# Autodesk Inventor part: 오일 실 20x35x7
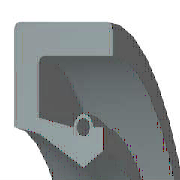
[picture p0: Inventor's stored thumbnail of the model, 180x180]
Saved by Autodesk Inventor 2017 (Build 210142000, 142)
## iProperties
IsCustomPart: 1
Created: 2012-02
Part Number: 오일 실 20x35x7
Material: 고무
Description: 회전 샤프트 립 유형 실 2 - 금속 케이스
Document SubType Name: Modeling
Standard: ISO 6194/1
Designer: mduedu
Standards Organization: ISO
Language: ko-KR
Size Designation: 20x35x7-유형 2
Categories: <MemberInstance><Categories><Category DisplayName="샤프트 부품" InternalName="7f7aeb1f-a693-4053-b835-cee3144e0d98" Mnemonic="SHFT"><Category DisplayName="실링" Intern
Density: 0.93 g/cm^3
Appearance: 고무 - 검은색 - 버전 1.1
Author: mduedu
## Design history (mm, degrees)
node "WorkPlane2"
node "WorkPoint1"
node "WorkPlane3"
body "Solid1"
node "스케치1"
revolve "회전1" stored, may be unused: angle "d37" = 360 deg
fillet "모깎기1" dims "d38" = 0.35 (= 0.05 x b)
sketch "스케치2"
  geometry: L1 (16, -0.35)-(16.8, -0.35); L2 (16, 0)-(16, -0.35); L3 (17.5, 0)-(16, 0); L4 (17.5, -7)-(17.5, 0); L5 (12.22, -7)-(17.5, -7); L6 (11.283, -4.2)-(12.22, -7); L7 (10.601, -3.72)-(11.283, -4.2); L8 (10, -1.925)-(10.601, -3.72); L9 (10.789, -1.05)-(10, -1.925); L10 (12.664, -1.05)-(10.789, -1.05); L11 (12.664, -1.925)-(12.664, -1.05); L12 (12.664, -5.6)-(12.664, -3.325); L13 (13.664, -5.6)-(12.664, -5.6); L14 (13.664, -6.3)-(13.664, -5.6); L15 (16.8, -6.3)-(13.664, -6.3); L16 (16.8, -0.35)-(16.8, -6.3); L17 (0, -15.959)-(0, 2.029); L18 (0, -15.959)-(0, 2.029); L19 (0, -19.557)-(0, 5.626) reference; L20 (-5.2, 0)-(31.2, 0) reference; A1 r 0.7 centre (12.664, -2.625) between (12.664, -3.325) and (12.664, -1.925)
  constraints: 36 end point, 7 vertical, 6 horizontal, 2 collinear, 2 point on circle, 1 centre point, 1 parallel, 1 point on line
  dimensions: "d2" = 0.35 distance of L2.start L1.start (= 0.05 x b); "d4" = 7 distance of L4.start L3.start (= b); "d6" = 0.7 horizontal distance of L1.end L3.start (= 0.1 x b); "d8" = 0.7 horizontal distance of L15.start L4.start (= 0.1 x b); "d10" = 0.7 distance of L14.start L13.start (= 0.1 x b); "d12" = 0.7 vertical distance of L1.end L10.start (= 0.1 x b); "d14" = 0.875 distance of L11.start L10.start (= 0.125 x b); "d16" = 0.7 radius of A1 (= 0.1 x b); "d18" = 0 horizontal distance of A1.centre L12.end; "d20" = 0.875 vertical distance of L9.start L8.start (= 0.125 x b); "d22" = 1.79487 vertical distance of L8.start L7.start (= 0.25641 x b); "d24" = 2.8 vertical distance of L6.start L5.start (= 0.4 x b); "d26" = 1.5 distance of L3.start L2.start (= 0.1 x dd - 0.1 x Diam); "d28" = 0.78947 horizontal distance of L9.start L8.start (= 0.0526316 x dd - 0.0526316 x Diam); "d30" = 1.875 distance of L10.start L9.start (= 0.125 x dd - 0.125 x Diam); "d32" = 1 distance of L13.start L12.start (= 0.0666667 x dd - 0.0666667 x Diam); "d34" = 0.9375 horizontal distance of L6.start L5.start (= 0.0625 x dd - 0.0625 x Diam); "d36" = 0.68182 horizontal distance of L7.start L6.start (= 0.0454545 x dd - 0.0454545 x Diam); "msp_d39" = 20 diameter of L8.start L17 (= Diam); "msp_d40" = 35 diameter of L4 L17 (= dd)
other parameters: "dd" = 35 [user parameter; used in 7 equation terms], "Diam" = 20 [user parameter; used in 7 equation terms], "b" = 7 [user parameter; used in 13 equation terms], "d0" = -7 (computed from b), "d1" = 0.4 (derived), "d3" = 8 (derived), "d5" = 0.8 (derived), "d7" = 0.8 (derived), "d9" = 0.8 (derived), "d11" = 0.8 (derived), "d13" = 1 (derived), "d15" = 0.8 (derived), "d17" = 0 (derived), "d19" = 1 (derived), "d21" = 2.05128 (derived), "d23" = 3.2 (derived), "d25" = 2 (derived), "d27" = 1.05263 (derived), "d29" = 2.5 (derived), "d31" = 1.33333 (derived), "d33" = 1.25 (derived), "d35" = 0.90909 (derived), "d42" = 0
